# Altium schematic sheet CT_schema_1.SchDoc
size 581 x 258 mm
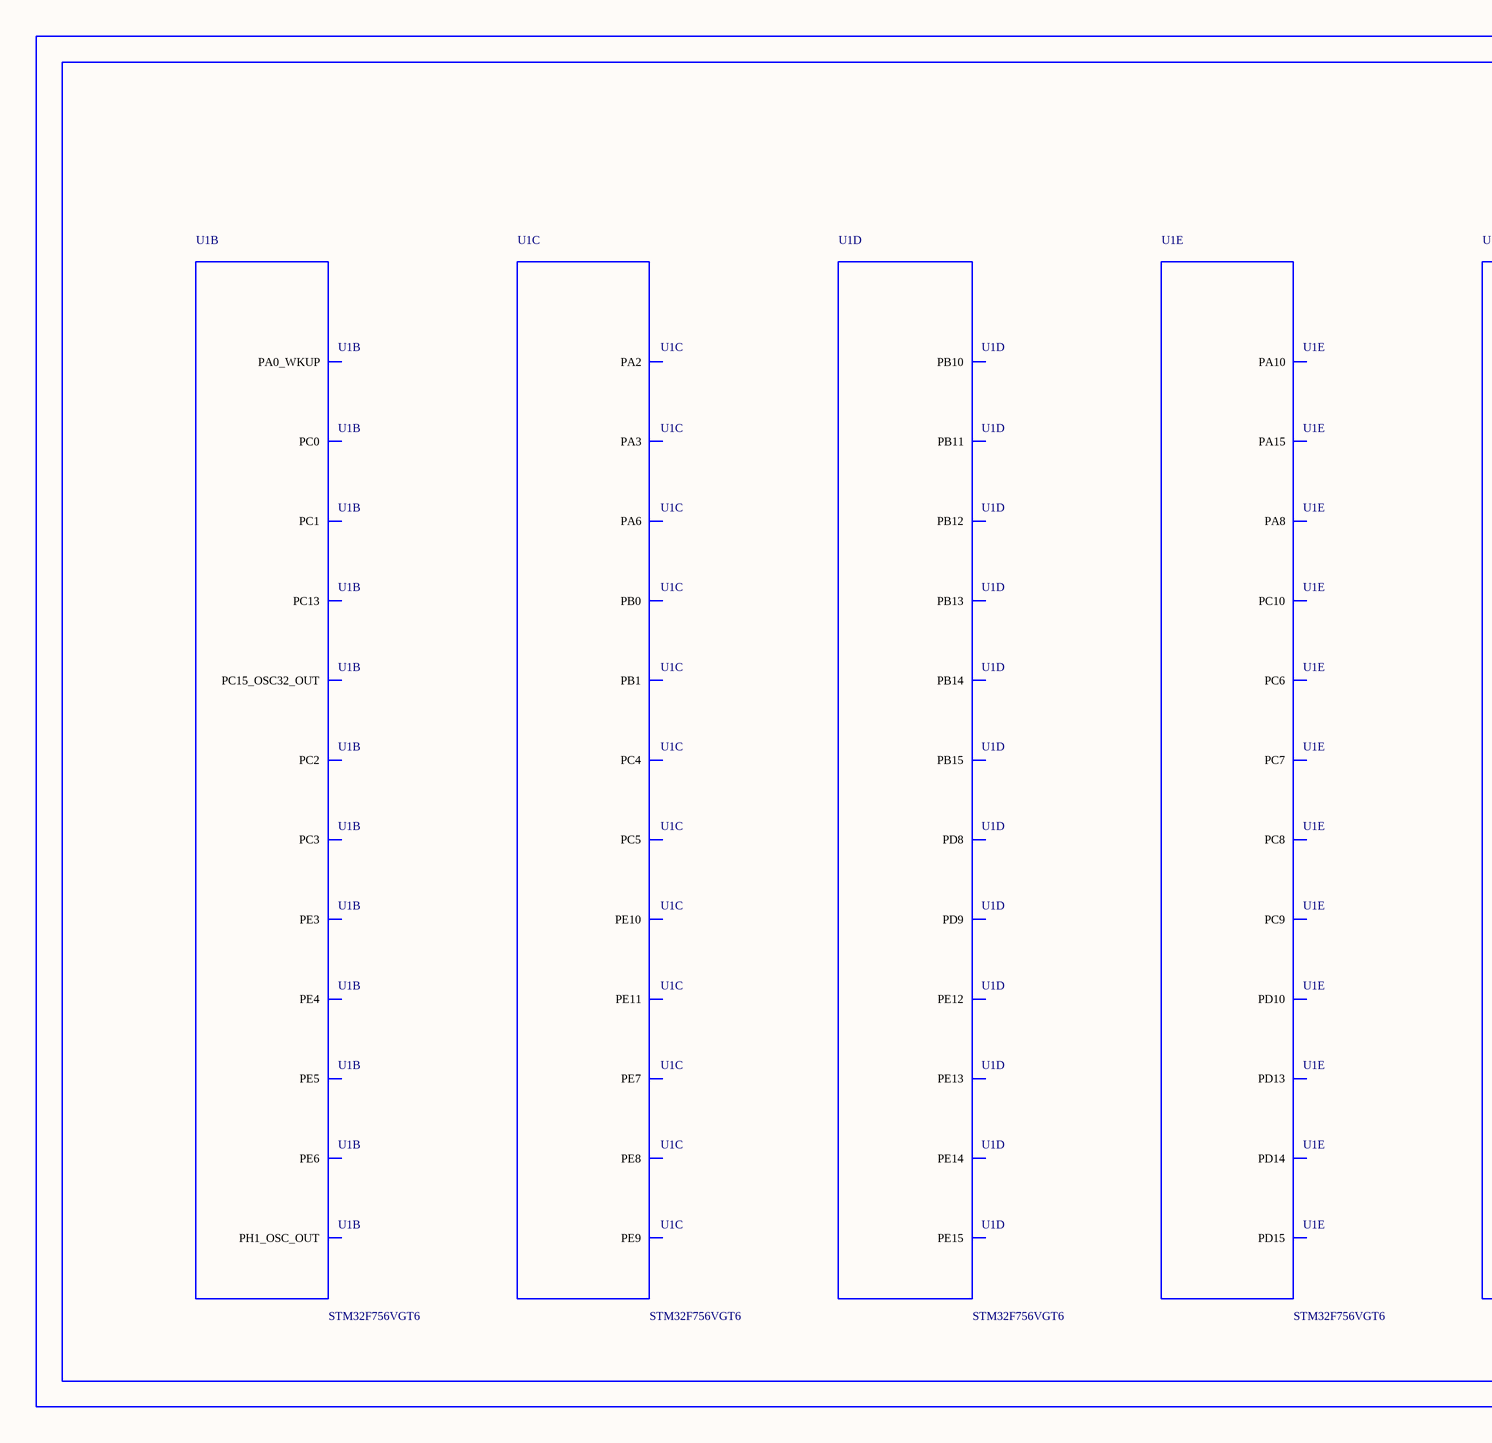
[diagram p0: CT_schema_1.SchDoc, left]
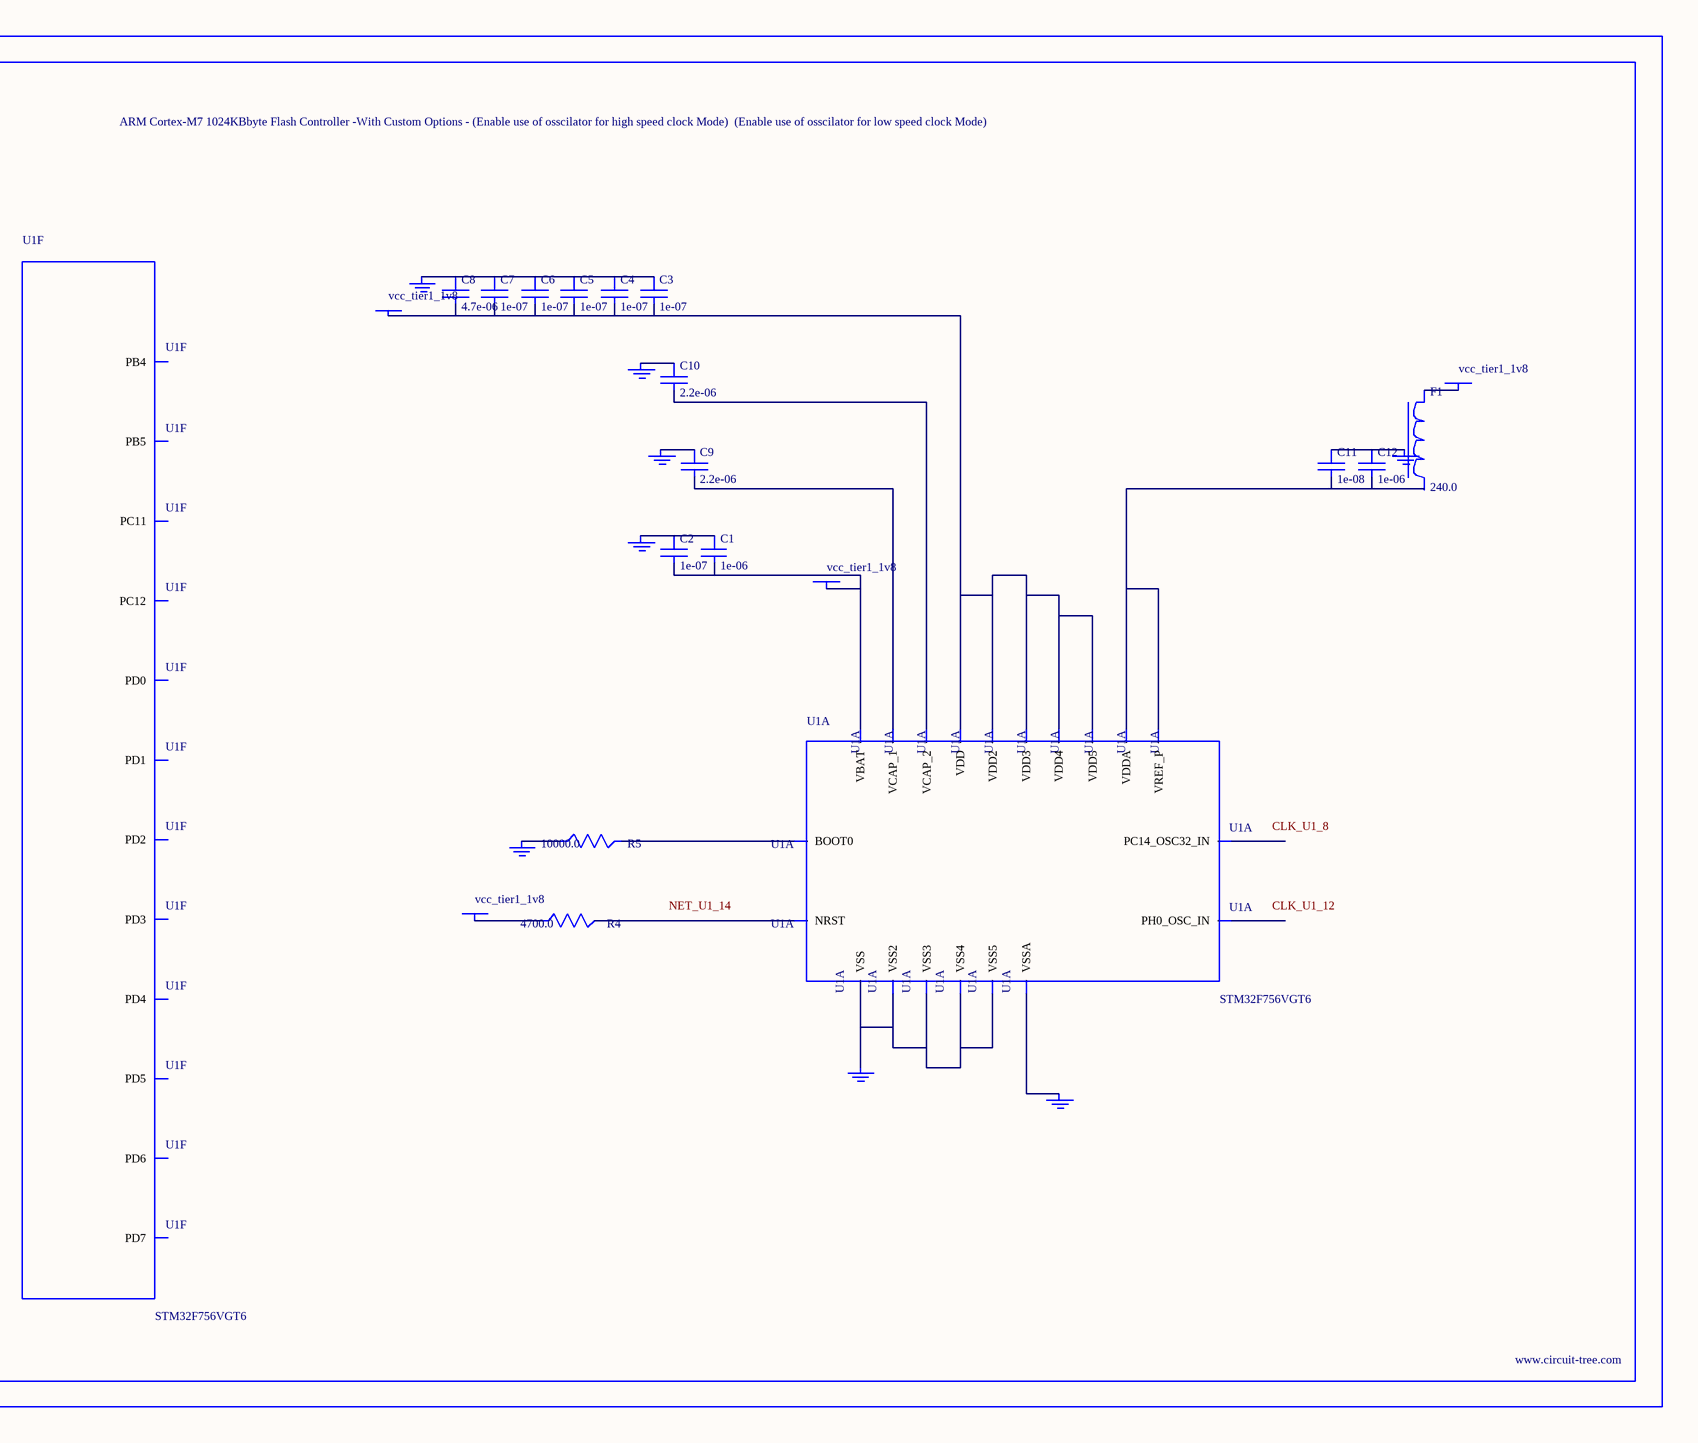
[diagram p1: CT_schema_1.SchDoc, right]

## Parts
BORDER0  (no value)
C1  1e-06  [C0603]
C2  1e-07  [C0603]
C3  1e-07  [C0603]
C4  1e-07  [C0603]
C5  1e-07  [C0603]
C6  1e-07  [C0603]
C7  1e-07  [C0603]
C8  4.7e-06  [C0603]
C9  2.2e-06  [C0603]
C10  2.2e-06  [C0603]
C11  1e-08  [C0603]
C12  1e-06  [C0603]
F1  240.0  [L0603]
GND_INSTANCE_0_0  (no value)
GND_INSTANCE_0_1  (no value)
GND_INSTANCE_0_2  (no value)
GND_INSTANCE_0_3  (no value)
GND_INSTANCE_0_4  (no value)
GND_INSTANCE_0_5  (no value)
GND_INSTANCE_0_6  (no value)
GND_INSTANCE_0_7  (no value)
POWER_INSTANCE_0_0  vcc_tier1_1v8
POWER_INSTANCE_0_1  vcc_tier1_1v8
POWER_INSTANCE_0_2  vcc_tier1_1v8
POWER_INSTANCE_0_3  vcc_tier1_1v8
R4  4700.0  [R0603]
R5  10000.0  [R0603]
U1  STM32F756VGT6  [LQFP100]  (parts A,B,C,D,E,F of 10)

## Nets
NetC1_1: C1.1 C2.1 GND_INSTANCE_0_0.0(GND)
NetC1_2: C1.2 C2.2 POWER_INSTANCE_0_0.0(PWR) U1.6(VBAT)
NetC3_1: C3.1 C4.1 C5.1 C6.1 C7.1 C8.1 GND_INSTANCE_0_1.0(GND)
NetC3_2: C3.2 C4.2 C5.2 C6.2 C7.2 C8.2 POWER_INSTANCE_0_1.0(PWR) U1.11(VDD) U1.27(VDD2) U1.50(VDD3) U1.75(VDD4) U1.100(VDD5)
NetC9_1: C9.1 GND_INSTANCE_0_4.0(GND)
NetC9_2: C9.2 U1.48(VCAP_1)
NetC10_1: C10.1 GND_INSTANCE_0_5.0(GND)
NetC10_2: C10.2 U1.73(VCAP_2)
NetC11_1: C11.1 C12.1 GND_INSTANCE_0_3.0(GND)
NetC11_2: C11.2 C12.2 U1.20(VREF_P) U1.21(VDDA)
NetF1_1: F1.1 POWER_INSTANCE_0_2.0(PWR)
NetGND_INSTANCE_0_2_0: GND_INSTANCE_0_2.0(GND) U1.19(VSSA)
NetGND_INSTANCE_0_6_0: GND_INSTANCE_0_6.0(GND) R5.1
NetGND_INSTANCE_0_7_0: GND_INSTANCE_0_7.0(GND) U1.10(VSS) U1.26(VSS2) U1.49(VSS3) U1.74(VSS4) U1.99(VSS5)
NetPOWER_INSTANCE_0_3_0: POWER_INSTANCE_0_3.0(PWR) R4.1
NetR4_2: R4.2 U1.14(NRST)
NetR5_2: R5.2 U1.94(BOOT0)

Not connected (* = marked no-connect by the designer): F1 2; U1 2(PE3) 3(PE4) 4(PE5) 5(PE6) 7(PC13) 8(PC14_OSC32_IN) 9(PC15_OSC32_OUT) 12(PH0_OSC_IN) 13(PH1_OSC_OUT) 15(PC0) 16(PC1) 17(PC2) 18(PC3) 22(PA0_WKUP) 24(PA2) 25(PA3) 30(PA6) 32(PC4) 33(PC5) 34(PB0) 35(PB1) 37(PE7) 38(PE8) 39(PE9) 40(PE10) 41(PE11) 42(PE12) 43(PE13) 44(PE14) 45(PE15) 46(PB10) 47(PB11) 51(PB12) 52(PB13) 53(PB14) 54(PB15) 55(PD8) 56(PD9) 57(PD10) 60(PD13) 61(PD14) 62(PD15) 63(PC6) 64(PC7) 65(PC8) 66(PC9) 67(PA8) 69(PA10) 77(PA15) 78(PC10) 79(PC11) 80(PC12) 81(PD0) 82(PD1) 83(PD2) 84(PD3) 85(PD4) 86(PD5) 87(PD6) 88(PD7) 90(PB4) 91(PB5)

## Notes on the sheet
- Labels drawn without touching a wire or pin: CLK_U1_8, CLK_U1_12, NET_U1_14

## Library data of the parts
BORDER0 = BORDER_PAGE0
C1 C12 = C0603C105K3RACTU
C2-C7 = 06035C104K4Z2A
C8 = GRM188R6YA475KE15D
C9 C10 = C0603C225K8RACTU
C11 = 06035C103K4Z2A
F1 = Z0603C241ASMST
GND_INSTANCE_0_0-GND_INSTANCE_0_7 = GND
POWER_INSTANCE_0_0-POWER_INSTANCE_0_3 = PWR
R4 = RC0603JR-074K7L
R5 = RC0603JR-0710KL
